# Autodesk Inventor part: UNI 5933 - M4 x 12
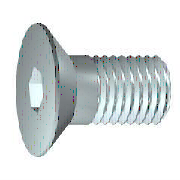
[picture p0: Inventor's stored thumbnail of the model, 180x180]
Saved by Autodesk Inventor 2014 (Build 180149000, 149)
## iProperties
Created: 2007-03
Part Number: UNI 5933 - M4 x 12
Material: Steel, Mild
Description: Countersunk Screw
Document SubType Name: Modeling
Standard: UNI 5933
Designer: Autodesk, Inc.
Standards Organization: UNI
Language: en-US
Size Designation: M4 x 12
Categories: <MemberInstance><Categories><Category DisplayName="Fasteners" InternalName="e4da775c-781d-43d5-af7c-5136215cf5a6" Mnemonic="FSTN"><Category DisplayName="Bolts"
Density: 7.86 g/cm^3
Mass: 1.43572 g
Surface Area: 2.50381 cm^2
Volume: 0.182661 cm^3
Appearance: Steel
IsCustomPart: 0
Author: Autodesk, Inc.
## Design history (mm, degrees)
body "Solid1"
revolve "Body" stored, may be unused: angle "d13" = 90 deg
sketch "Sketch2"
  geometry: L1 (0, -5.348)-(0, 5.348) reference; L2 (-5.348, 0)-(5.348, 0) reference; L3 (1.443, 0)-(0.722, -1.25); L4 (0.722, -1.25)-(-0.722, -1.25); L5 (-0.722, -1.25)-(-1.443, 0); L6 (-1.443, 0)-(-0.722, 1.25); L7 (-0.722, 1.25)-(0.722, 1.25); L8 (0.722, 1.25)-(1.443, 0); A1 r 1.443 centre (0, 0) between (0, 1.443) and (1.443, 0) reference; 2 further points
  constraints: 12 end point, 2 coincident, 2 point on circle, 2 point on line, 12 other
extrude "Slot" join sketch "Sketch2" taper "d14" = 0 deg; stored distance "d30" = 10
feature "Thread" dims "d15" = 7.95 (= GEL), "d16" = 0
chamfer "Chamfer1" distance "d17" = 0.42941 (= -0.5 x SPD + 0.5 x GD); stored, may be unused: second distance "d18" = 0.42941 (= GUL), angle "d39" = 45 deg
workplane "Work Plane1"
sketch "Sketch1"
  geometry: L1 (12, 0)-(12, 2); L2 (12, 2)-(4.05, 2); L3 (4.05, 2)-(3.621, 2); L4 (0, 3.82)-(0, 1.443); L5 (0, 1.443)-(1.55, 1.443); L6 (1.55, 1.443)-(2.383, 0); L7 (2.383, 0)-(12, 0); L8 (0, 3.82)-(0.48, 3.82); L9 (0.48, 3.82)-(2.3, 2); L10 (3.621, 2)-(2.3, 2); L11 (4.05, 2)-(2.3, 2); L12 (2.3, 2)-(2.3, 2); L13 (-2.4, 0)-(14.4, 0) reference; L14 (0, -0.764)-(0, 4.584) reference
  constraints: 24 end point, 4 collinear, 3 parallel
  dimensions: "d0" = 12 distance between parallel lines of L4 L1 (= NLG); "d1" = 7.95 distance from line of L2.end L1 (= GEL); "d2" = 1.55 distance from line of L5.end L4 (= INTI); "d3" = 4 diameter of L2 L7 (= GD); "d6" = 2.3 distance from line of L9.end L4 (= KOH); "d7" = 45 deg angle of L9 L7 (= 0.5 x SEWI); "d8" = 2.88675 diameter of L5 L7 (= 1.1547 x SW); "d9" = 60 deg angle of L6 L7; "d10" = 7.64 diameter of L8 L7 (= KOD); "d11" = 4 diameter of L10 L7 (= BDM); "d12" = 0.42941 distance of L3.end L2.end (= GAL)
other parameters: "NLG" = 12 [user parameter; used in 1 equation term], "INTI" = 1.55 [user parameter; used in 1 equation term], "GEL" = 7.95 [user parameter; used in 2 equation terms], "GAL" = 0.42941 (= 0.61345 x PTC) [user parameter; used in 1 equation term], "KOH" = 2.3 [user parameter; used in 1 equation term], "KOD" = 7.64 [user parameter; used in 1 equation term], "GUL" = 0.42941 (= 0.61345 x PTC) [user parameter; used in 1 equation term], "SPD" = 3.14117 (= NND - 1.2269 x PTC) [user parameter; used in 1 equation term], "BDM" = 4 (= NND) [user parameter; used in 1 equation term], "GD" = 4 (= NND) [user parameter; used in 2 equation terms], "SEWI" = 90 deg [user parameter; used in 1 equation term], "d20" = 0, "SW" = 2.5 [user parameter; used in 2 equation terms], "d43" = 0, "d44" = 0, "TOA" = 30 deg [user parameter], "GD1" = 3.14117 (= THREADDIA - 1.2269 x PTC) [user parameter], "EPV" = 4.3 [user parameter], "THREADDIA" = 4 [user parameter; used in 1 equation term], "TPU" = 14.28571 (computed from PTC) [user parameter], "PTC" = 0.7 [user parameter; used in 5 equation terms], "NND" = 4 [user parameter; used in 3 equation terms], "E0" = 2.8875 (= 1.155 x SW) [user parameter]
